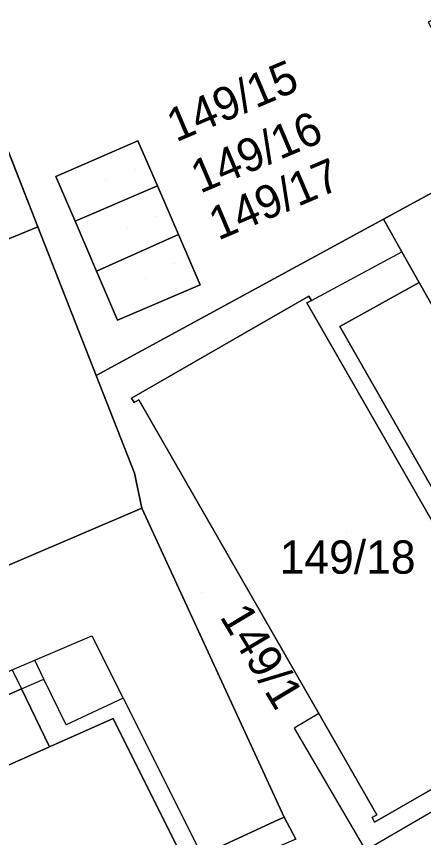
# Model space of a CAD drawing. Extents: x -264070 to -262271, y -1238894 to -1238141.
# Drawn here: x -263238.46 to -263213.95, y -1238690.43 to -1238641.04 of the extents above; entities that cross this region are included whole.
import ezdxf

# ---------------------------------------------------------------- set-up
doc = ezdxf.new("R2010")
doc.units = 0
for name, color, linetype in [('body_kn', 7, 'Continuous'), ('kladpar_druhypozemkov', 7, 'Continuous'), ('kladpar_hranice', 7, 'Continuous'), ('kladpar_parcelnecisla', 7, 'Continuous'), ('kladpar_plochy', 7, 'Continuous'), ('kladpar_sipky', 7, 'Continuous'), ('zappar_hrandruhpozemk', 7, 'Continuous')]:
    doc.layers.add(name, color=color, linetype=linetype)

msp = doc.modelspace()

# ---------------------------------------------------------------- linework, layer by layer
at = {"layer": 'body_kn'}
for p, q in [((-263231.16, -1238648.52), (-263231.16, -1238648.52)), ((-263231.16, -1238648.52), (-263231.16, -1238648.52)), ((-263236.08, -1238650.67), (-263236.08, -1238650.67)), ((-263229.97, -1238651.24), (-263229.97, -1238651.24)), ((-263229.97, -1238651.24), (-263229.97, -1238651.24)), ((-263216.36, -1238653.24), (-263216.36, -1238653.24)), ((-263216.36, -1238653.24), (-263216.36, -1238653.24)), ((-263237.17, -1238653.7), (-263237.17, -1238653.7)), ((-263237.17, -1238653.7), (-263237.17, -1238653.7)), ((-263234.92, -1238653.36), (-263234.92, -1238653.36)), ((-263228.7, -1238654.17), (-263228.7, -1238654.17)), ((-263228.7, -1238654.17), (-263228.7, -1238654.17)), ((-263215.25, -1238655.2), (-263215.25, -1238655.2)), ((-263233.64, -1238656.36), (-263233.64, -1238656.36)), ((-263227.4, -1238657.19), (-263227.4, -1238657.19)), ((-263214.22, -1238657.04), (-263214.22, -1238657.04)), ((-263220.85, -1238657.86), (-263220.85, -1238657.86)), ((-263220.7, -1238658.12), (-263220.7, -1238658.12)), ((-263220.7, -1238658.12), (-263220.7, -1238658.12)), ((-263220.98, -1238658.28), (-263220.98, -1238658.28)), ((-263232.38, -1238659.31), (-263232.38, -1238659.31)), ((-263219, -1238659.69), (-263219, -1238659.69)), ((-263219, -1238659.69), (-263219, -1238659.69)), ((-263233.66, -1238662.65), (-263233.66, -1238662.65)), ((-263231.54, -1238664), (-263231.54, -1238664)), ((-263231.54, -1238664), (-263231.54, -1238664)), ((-263231.1, -1238664.11), (-263231.1, -1238664.11)), ((-263231.38, -1238664.27), (-263231.38, -1238664.27)), ((-263231.35, -1238668.52), (-263231.35, -1238668.52)), ((-263230.91, -1238670.62), (-263230.91, -1238670.62)), ((-263230.91, -1238670.62), (-263230.91, -1238670.62)), ((-263233.92, -1238678.29), (-263233.92, -1238678.29)), ((-263237.36, -1238679.77), (-263237.36, -1238679.77)), ((-263237.36, -1238679.77), (-263237.36, -1238679.77)), ((-263236.8, -1238680.9), (-263236.8, -1238680.9)), ((-263236.8, -1238680.9), (-263236.8, -1238680.9)), ((-263238.16, -1238681.49), (-263238.16, -1238681.49)), ((-263238.16, -1238681.49), (-263238.16, -1238681.49)), ((-263232.04, -1238682.04), (-263232.04, -1238682.04)), ((-263232.04, -1238682.04), (-263232.04, -1238682.04)), ((-263232.63, -1238683.27), (-263232.63, -1238683.27)), ((-263220.26, -1238682.97), (-263220.26, -1238682.97)), ((-263220.26, -1238682.97), (-263220.26, -1238682.97)), ((-263235.46, -1238683.65), (-263235.46, -1238683.65)), ((-263221.75, -1238683.85), (-263221.75, -1238683.85)), ((-263236.47, -1238684.98), (-263236.47, -1238684.98)), ((-263236.47, -1238684.98), (-263236.47, -1238684.98)), ((-263222.34, -1238689.2), (-263222.34, -1238689.2)), ((-263217.05, -1238689.23), (-263217.05, -1238689.23)), ((-263216.76, -1238689.06), (-263216.76, -1238689.06)), ((-263222.92, -1238689.47), (-263222.92, -1238689.47)), ((-263216.9, -1238689.5), (-263216.9, -1238689.5))]:
    msp.add_line(p, q, dxfattribs=at)
at = {"layer": 'kladpar_druhypozemkov'}
for p, q in [((-263233.07, -1238650.86), (-263233.07, -1238650.86)), ((-263231.8, -1238653.8), (-263231.8, -1238653.8)), ((-263230.67, -1238656.81), (-263230.67, -1238656.81)), ((-263218.61, -1238672.08), (-263218.61, -1238672.08)), ((-263227.32, -1238675.67), (-263227.32, -1238675.67))]:
    msp.add_line(p, q, dxfattribs=at)
at = {"layer": 'kladpar_hranice'}
for points in [[(-263170.34, -1238624.54), (-263183.61, -1238631.76), (-263181.86, -1238635), (-263197.98, -1238643.41), (-263199.57, -1238640.48), (-263200.92, -1238637.98), (-263202.43, -1238635.22), (-263207.92, -1238638.32), (-263206.48, -1238640.95), (-263205.14, -1238643.39), (-263205.68, -1238643.67), (-263207.05, -1238641.14), (-263208.43, -1238638.62), (-263213.68, -1238641.4), (-263212.31, -1238643.91), (-263210.94, -1238646.43), (-263209.32, -1238649.41), (-263216.36, -1238653.24), (-263233.66, -1238662.65), (-263237.17, -1238653.7), (-263241.51, -1238642.66)], [(-263241.51, -1238642.66), (-263237.17, -1238653.7), (-263255.99, -1238661.44)], [(-263231.16, -1238648.52), (-263229.97, -1238651.24), (-263234.92, -1238653.36), (-263236.08, -1238650.67), (-263231.16, -1238648.52)], [(-263227.4, -1238657.19), (-263228.7, -1238654.17), (-263229.97, -1238651.24), (-263231.16, -1238648.52), (-263236.08, -1238650.67), (-263234.92, -1238653.36), (-263233.64, -1238656.36), (-263232.38, -1238659.31), (-263227.4, -1238657.19)], [(-263212.99, -1238659.21), (-263214.22, -1238657.04), (-263215.25, -1238655.2), (-263216.36, -1238653.24), (-263209.32, -1238649.41)], [(-263229.97, -1238651.24), (-263228.7, -1238654.17), (-263233.64, -1238656.36), (-263234.92, -1238653.36), (-263229.97, -1238651.24)], [(-263221.65, -1238690.52), (-263222.34, -1238689.2), (-263230.91, -1238670.62), (-263231.35, -1238668.52), (-263233.66, -1238662.65), (-263216.36, -1238653.24)], [(-263216.36, -1238653.24), (-263215.25, -1238655.2), (-263214.22, -1238657.04), (-263219, -1238659.69), (-263208.1, -1238678.73)], [(-263237.17, -1238653.7), (-263233.66, -1238662.65), (-263231.35, -1238668.52), (-263230.91, -1238670.62), (-263248.99, -1238678.33), (-263255.99, -1238661.44), (-263237.17, -1238653.7)], [(-263228.7, -1238654.17), (-263227.4, -1238657.19), (-263232.38, -1238659.31), (-263233.64, -1238656.36), (-263228.7, -1238654.17)], [(-263219, -1238659.69), (-263214.22, -1238657.04), (-263212.99, -1238659.21), (-263199.82, -1238682.86), (-263204.26, -1238685.39), (-263205, -1238683.95), (-263205.54, -1238683.12), (-263205.96, -1238682.54), (-263206.97, -1238682.66), (-263208.4, -1238680.17), (-263208, -1238679.55), (-263207.92, -1238679.17), (-263208.1, -1238678.73), (-263219, -1238659.69)], [(-263231.54, -1238664), (-263220.85, -1238657.86), (-263220.7, -1238658.12), (-263220.98, -1238658.28), (-263208.4, -1238680.17), (-263206.97, -1238682.66), (-263206.64, -1238683.24), (-263206.35, -1238683.08), (-263206.19, -1238683.34), (-263216.9, -1238689.5), (-263217.05, -1238689.23), (-263216.76, -1238689.06), (-263220.26, -1238682.97), (-263231.1, -1238664.11), (-263231.38, -1238664.27), (-263231.54, -1238664)], [(-263208.4, -1238680.17), (-263220.98, -1238658.28), (-263220.7, -1238658.12), (-263220.85, -1238657.86), (-263231.54, -1238664), (-263231.38, -1238664.27), (-263231.1, -1238664.11), (-263220.26, -1238682.97), (-263216.76, -1238689.06), (-263217.05, -1238689.23), (-263216.9, -1238689.5), (-263206.19, -1238683.34)], [(-263230.91, -1238670.62), (-263222.34, -1238689.2), (-263222.92, -1238689.47), (-263227.3, -1238691.49), (-263228.31, -1238691.94), (-263232.63, -1238683.27), (-263236.47, -1238684.98), (-263238.16, -1238681.49), (-263245.16, -1238684.57), (-263245.4, -1238684.06), (-263258.27, -1238689.4), (-263258.51, -1238688.86), (-263262, -1238690.36), (-263264.45, -1238684.93), (-263260.93, -1238683.43), (-263248.99, -1238678.33), (-263230.91, -1238670.62)], [(-263262, -1238690.36), (-263258.51, -1238688.86), (-263258.27, -1238689.4), (-263245.4, -1238684.06), (-263245.16, -1238684.57), (-263238.16, -1238681.49), (-263236.47, -1238684.98), (-263256.54, -1238693.92), (-263253.41, -1238701.42), (-263256.92, -1238703.33), (-263255.91, -1238705.32), (-263257.37, -1238705.95), (-263259.33, -1238706.8), (-263260.49, -1238704.4), (-263264.03, -1238696.92), (-263262.83, -1238696.41), (-263267.46, -1238686.21), (-263264.45, -1238684.93), (-263262, -1238690.36)], [(-263236.47, -1238684.98), (-263232.63, -1238683.27), (-263228.31, -1238691.94), (-263227.3, -1238691.49), (-263222.92, -1238689.47), (-263222.34, -1238689.2), (-263221.65, -1238690.52), (-263224.27, -1238691.65), (-263226.5, -1238692.62), (-263228.7, -1238693.57), (-263230.91, -1238694.52), (-263233.11, -1238695.47), (-263235.32, -1238696.42), (-263237.52, -1238697.37), (-263239.72, -1238698.33)], [(-263256.54, -1238693.92), (-263236.47, -1238684.98)]]:
    msp.add_lwpolyline(points, dxfattribs=at)
at = {"layer": 'kladpar_plochy'}
for p, q in [((-263237.17, -1238653.7), (-263241.51, -1238642.66)), ((-263231.16, -1238648.52), (-263236.08, -1238650.67)), ((-263229.97, -1238651.24), (-263231.16, -1238648.52)), ((-263209.32, -1238649.41), (-263216.36, -1238653.24)), ((-263236.08, -1238650.67), (-263234.92, -1238653.36)), ((-263228.7, -1238654.17), (-263229.97, -1238651.24)), ((-263216.36, -1238653.24), (-263233.66, -1238662.65)), ((-263233.66, -1238662.65), (-263237.17, -1238653.7)), ((-263234.92, -1238653.36), (-263233.64, -1238656.36)), ((-263227.4, -1238657.19), (-263228.7, -1238654.17)), ((-263233.64, -1238656.36), (-263232.38, -1238659.31)), ((-263232.38, -1238659.31), (-263227.4, -1238657.19))]:
    msp.add_line(p, q, dxfattribs=at)
for points in [[(-263241.51, -1238642.66), (-263237.17, -1238653.7), (-263255.99, -1238661.44)], [(-263212.99, -1238659.21), (-263214.22, -1238657.04), (-263215.25, -1238655.2), (-263216.36, -1238653.24), (-263209.32, -1238649.41)], [(-263221.65, -1238690.52), (-263222.34, -1238689.2), (-263230.91, -1238670.62), (-263231.35, -1238668.52), (-263233.66, -1238662.65), (-263216.36, -1238653.24), (-263215.25, -1238655.2), (-263214.22, -1238657.04), (-263219, -1238659.69), (-263208.1, -1238678.73)], [(-263208.4, -1238680.17), (-263220.98, -1238658.28), (-263220.7, -1238658.12), (-263220.85, -1238657.86), (-263231.54, -1238664), (-263231.38, -1238664.27), (-263231.1, -1238664.11), (-263220.26, -1238682.97), (-263216.76, -1238689.06), (-263217.05, -1238689.23), (-263216.9, -1238689.5), (-263206.19, -1238683.34)], [(-263256.54, -1238693.92), (-263236.47, -1238684.98), (-263232.63, -1238683.27), (-263228.31, -1238691.94), (-263227.3, -1238691.49), (-263222.92, -1238689.47), (-263222.34, -1238689.2), (-263221.65, -1238690.52), (-263224.27, -1238691.65), (-263226.5, -1238692.62), (-263228.7, -1238693.57), (-263230.91, -1238694.52), (-263233.11, -1238695.47), (-263235.32, -1238696.42), (-263237.52, -1238697.37), (-263239.72, -1238698.33)]]:
    msp.add_lwpolyline(points, dxfattribs=at)
for points in [[(-263231.16, -1238648.52), (-263229.97, -1238651.24), (-263234.92, -1238653.36), (-263236.08, -1238650.67)], [(-263229.97, -1238651.24), (-263228.7, -1238654.17), (-263233.64, -1238656.36), (-263234.92, -1238653.36)], [(-263237.17, -1238653.7), (-263233.66, -1238662.65), (-263231.35, -1238668.52), (-263230.91, -1238670.62), (-263248.99, -1238678.33), (-263255.99, -1238661.44)], [(-263228.7, -1238654.17), (-263227.4, -1238657.19), (-263232.38, -1238659.31), (-263233.64, -1238656.36)], [(-263219, -1238659.69), (-263214.22, -1238657.04), (-263212.99, -1238659.21), (-263199.82, -1238682.86), (-263204.26, -1238685.39), (-263205, -1238683.95), (-263205.54, -1238683.12), (-263205.96, -1238682.54), (-263206.97, -1238682.66), (-263208.4, -1238680.17), (-263208, -1238679.55), (-263207.92, -1238679.17), (-263208.1, -1238678.73)], [(-263231.54, -1238664), (-263220.85, -1238657.86), (-263220.7, -1238658.12), (-263220.98, -1238658.28), (-263208.4, -1238680.17), (-263206.97, -1238682.66), (-263206.64, -1238683.24), (-263206.35, -1238683.08), (-263206.19, -1238683.34), (-263216.9, -1238689.5), (-263217.05, -1238689.23), (-263216.76, -1238689.06), (-263220.26, -1238682.97), (-263231.1, -1238664.11), (-263231.38, -1238664.27)], [(-263230.91, -1238670.62), (-263222.34, -1238689.2), (-263222.92, -1238689.47), (-263227.3, -1238691.49), (-263228.31, -1238691.94), (-263232.63, -1238683.27), (-263236.47, -1238684.98), (-263238.16, -1238681.49), (-263245.16, -1238684.57), (-263245.4, -1238684.06), (-263258.27, -1238689.4), (-263258.51, -1238688.86), (-263262, -1238690.36), (-263264.45, -1238684.93), (-263260.93, -1238683.43), (-263248.99, -1238678.33)], [(-263262, -1238690.36), (-263258.51, -1238688.86), (-263258.27, -1238689.4), (-263245.4, -1238684.06), (-263245.16, -1238684.57), (-263238.16, -1238681.49), (-263236.47, -1238684.98), (-263256.54, -1238693.92), (-263253.41, -1238701.42), (-263256.92, -1238703.33), (-263255.91, -1238705.32), (-263257.37, -1238705.95), (-263259.33, -1238706.8), (-263260.49, -1238704.4), (-263264.03, -1238696.92), (-263262.83, -1238696.41), (-263267.46, -1238686.21), (-263264.45, -1238684.93)]]:
    msp.add_lwpolyline(points, close=True, dxfattribs=at)
at = {"layer": 'kladpar_sipky'}
for p, q in [((-263231.3, -1238650.26), (-263231.3, -1238650.26)), ((-263230.03, -1238653.06), (-263230.03, -1238653.06)), ((-263228.96, -1238655.91), (-263228.96, -1238655.91))]:
    msp.add_line(p, q, dxfattribs=at)
at = {"layer": 'zappar_hrandruhpozemk'}
for p, q in [((-263220.7, -1238658.12), (-263215.25, -1238655.2)), ((-263237.36, -1238679.77), (-263233.92, -1238678.29)), ((-263236.8, -1238680.9), (-263237.36, -1238679.77)), ((-263238.72, -1238680.35), (-263238.16, -1238681.49)), ((-263238.16, -1238681.49), (-263236.8, -1238680.9)), ((-263235.46, -1238683.65), (-263236.8, -1238680.9)), ((-263232.04, -1238682.04), (-263235.46, -1238683.65)), ((-263220.26, -1238682.97), (-263221.75, -1238683.85)), ((-263221.75, -1238683.85), (-263217.44, -1238691.19)), ((-263217.44, -1238691.19), (-263205, -1238683.95))]:
    msp.add_line(p, q, dxfattribs=at)
for points in [[(-263233.92, -1238678.29), (-263232.04, -1238682.04), (-263227.3, -1238691.49)], [(-263258.51, -1238688.86), (-263238.72, -1238680.35), (-263237.36, -1238679.77)]]:
    msp.add_lwpolyline(points, dxfattribs=at)

# ---------------------------------------------------------------- texts
at = {"layer": 'kladpar_parcelnecisla'}
for s, rotation, p in [('149/15', 23, (-263228.851, -1238648.627)), ('149/16', 23, (-263227.4, -1238651.716)), ('149/17', 23, (-263226.316, -1238654.537)), ('149/1', 301, (-263226.256, -1238677.145))]:
    msp.add_text(s, height=2, rotation=rotation, dxfattribs=at).set_placement(p)
msp.add_text('149/18', height=2, dxfattribs=at).set_placement((-263222.615, -1238674.56))

doc.saveas('drawing.dxf')
